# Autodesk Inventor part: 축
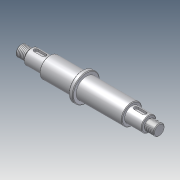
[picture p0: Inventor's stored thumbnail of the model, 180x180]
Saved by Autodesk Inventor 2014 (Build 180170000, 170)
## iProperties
Company: 한국ATC센터
Created: 2015-02
Part Number: 축
Document SubType Name: Modeling
Designer: KYOUNG IL JANG
Density: 1 g/cm^3
Material: 일반
Appearance: 기본값
Author: KYOUNG IL JANG
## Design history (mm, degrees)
sketch "스케치1"
  geometry: L1 (0, 0)-(203, 0); L2 (203, 0)-(203, 8); L3 (203, 8)-(189.5, 8); L4 (189.5, 8)-(189.5, 7); L5 (189.5, 7)-(188, 7); L6 (188, 7)-(188, 11); L7 (188, 11)-(163, 11); L8 (163, 11)-(163, 15); L9 (163, 15)-(96, 15); L10 (96, 15)-(96, 20); L11 (96, 20)-(90, 20); L12 (90, 20)-(90, 15); L13 (90, 15)-(42, 15); L14 (42, 15)-(42, 11); L15 (42, 11)-(15, 11); L16 (15, 11)-(15, 7); L17 (15, 7)-(13.5, 7); L18 (0, 8)-(0, 0); L19 (0, 8)-(13.5, 8); L20 (13.5, 8)-(13.5, 7)
  constraints: 40 end point, 16 parallel, 3 perpendicular, 1 collinear, 1 horizontal
  dimensions: "d0" = 16 diameter of L3 L1; "d1" = 14 diameter of L5 L1; "d2" = 22 diameter of L7 L1; "d3" = 30 diameter of L9 L1; "d4" = 40 diameter of L11 L1; "d5" = 16 diameter of L19 L1; "d6" = 22 diameter of L15 L1; "d8" = 1.5 distance of L16.end L17.end; "d9" = 15 distance between parallel lines of L16 L18; "d10" = 27 distance between parallel lines of L14 L16; "d11" = 48 distance between parallel lines of L12 L14; "d15" = 203 distance of L1.start L1.end; "d16" = 1.5 distance of L4.end L5.end; "d17" = 14 diameter of L17 L1; "d36" = 15 distance between parallel lines of L6 L2; "d37" = 25 distance between parallel lines of L6 L8; "d38" = 6 distance between parallel lines of L10 L12
revolve "회전1" sketch "스케치1" stored, may be unused: angle "d18" = 90 deg
feature "스레드1" dims "d19" = 10, "d20" = 0
feature "스레드2" dims "d21" = 10, "d22" = 0
chamfer "모따기1" distance "d23" = 1; stored, may be unused: second distance "d24" = 2, angle "d25" = 45 deg
node "작업 평면1"
sketch "스케치2"
  geometry: L1 (-6.5, 3)-(5.5, 3); L2 (5.5, -3)-(-6.5, -3); L3 (-13.5, -10)-(-13.5, 10) reference; L4 (140.5, 3)-(152.5, 3); L5 (152.5, -3)-(140.5, -3); L6 (159.5, 10)-(159.5, -10) reference; A1 r 3 centre (5.5, 0) between (5.5, -3) and (5.5, 3); A2 r 3 centre (-6.5, 0) between (-6.5, 3) and (-6.5, -3); A3 r 3 centre (152.5, 0) between (152.5, -3) and (152.5, 3); A4 r 3 centre (140.5, 0) between (140.5, 3) and (140.5, -3); 1 further point
  constraints: 8 end point, 8 point on circle, 8 tangent, 4 centre point, 2 horizontal, 2 horizontal alignment, 2 parallel
  dimensions: "d26" = 6 distance between parallel lines of L2 L1; "d27" = 18 dimension on A1 A2; "d28" = 4 distance edge to line of A2 L3; "d29" = 6 distance between parallel lines of L5 L4; "d30" = 18 dimension on A3 A4; "d31" = 4 distance edge to line of A3 L6
extrude "돌출1" cut sketch "스케치2" distance "d32" = 3.5; taper "d33" = 0 deg
node "솔리드1"
